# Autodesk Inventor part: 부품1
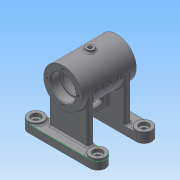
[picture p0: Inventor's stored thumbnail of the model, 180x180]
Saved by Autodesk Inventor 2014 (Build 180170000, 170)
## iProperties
Created: 2015-11
Part Number: 부품1
Material: 일반
Document SubType Name: Modeling
Designer: net
Density: 1 g/cm^3
Appearance: 기본값
Author: net
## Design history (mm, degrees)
sketch "스케치1"
  geometry: L1 (-40, -10)-(40, -10); L2 (40, 10)-(-40, 10); L3 (-40, -10)-(35.294, 8.824); L4 (40, -10)-(-40, 10); C1 r 3 at (-40, 0); C2 r 3 at (40, 0); A1 r 10 centre (-40, 0) between (-40, 10) and (-40, -10); A2 r 10 centre (40, 0) between (40, -10) and (40, 10); 1 further point
  constraints: 8 end point, 4 centre point, 4 point on circle, 2 coincident, 2 equal radius, 2 parallel, 2 tangent, 1 horizontal, 1 midpoint, 1 point on line
  dimensions: "d15" = 100 dimension on A2 A1; "d18" = 10 radius of A1; "d19" = 6 diameter of C1; "d20" = 151.928 deg angle of L3 L4; "d21" = 17.12016 distance from line of L3.end L4
extrude "돌출1" new body sketch "스케치1" distance "d22" = 10; taper "d23" = 0 deg
sketch "스케치2"
  geometry: C1 r 3 at (40, 0) reference; C2 r 3 at (-40, 0) reference; C3 r 10 at (-40, 0); C4 r 10 at (40, 0); A1 r 10 centre (-40, 0) between (-40, 10) and (-40, -10) reference; A2 r 10 centre (40, 0) between (40, -10) and (40, 10) reference; 1 further point
  constraints: 2 centre point, 2 coincident
  dimensions: "d24" = 20 diameter of C3; "d25" = 20 diameter of C4
extrude "돌출2" join sketch "스케치2" distance "d26" = 3; taper "d27" = 0 deg
sketch "스케치3"
  geometry: L1 (80, 0)-(0, 0) reference; L2 (15, 68)-(65, 68); L3 (65, 68)-(65, 0); L4 (65, 0)-(15, 0); L5 (15, 0)-(15, 68); 2 further points
  constraints: 8 end point, 2 midpoint, 2 parallel, 1 horizontal, 1 perpendicular
  dimensions: "d28" = 50 distance of L3.end L4.end; "d29" = 68 distance between parallel lines of L4 L2
extrude "돌출3" join sketch "스케치3" distance "d30" = 8; taper "d31" = 0 deg
sketch "스케치4"
  geometry: L1 (-40, -50)-(40, -50); L2 (40, -50)-(40, -70); L3 (40, -70)-(-40, -70); L4 (-40, -70)-(-40, -50); C1 r 3 at (-40, -60); C2 r 3 at (40, -60); 3 further points
  constraints: 8 end point, 2 centre point, 2 coincident, 2 midpoint, 2 parallel, 2 vertical alignment, 1 equal radius, 1 horizontal, 1 perpendicular, 4 other
  dimensions: "d34" = 80 distance between parallel lines of L2 L4; "d35" = 20 distance between parallel lines of L3 L1; "d36" = 40 distance from line of point (0, 0) L4 (= 0.5 x d34); "d37" = 50 distance from line of L1 point (0, 0); "d38" = 6 diameter of C1
extrude "돌출4" join sketch "스케치4" distance "d39" = 10; taper "d40" = 0 deg
sketch "스케치5"
  geometry: L1 (-40, -70)-(40, -70) reference; L2 (40, -50)-(-40, -50) reference; A1 r 10 centre (40, -60) between (40, -70) and (40, -50) reference; A2 r 10 centre (-40, -60) between (-40, -50) and (-40, -70) reference; 1 further point
extrude "돌출5" join sketch "스케치4" distance "d41" = 13; taper "d42" = 0 deg
extrude "돌출6" cut sketch "스케치4" stored distance "d43" = 13; taper "d44" = 0 deg
sketch "스케치6"
  geometry: L1 (0, 0)-(80, 0) reference; L2 (15, -68)-(65, -68); L3 (65, -68)-(65, 0); L4 (65, 0)-(15, 0); L5 (15, 0)-(15, -68); 1 further point
  constraints: 8 end point, 2 parallel, 1 horizontal, 1 perpendicular, 1 point on line
  dimensions: "d45" = 50 distance between parallel lines of L3 L5; "d46" = 68 distance between parallel lines of L2 L1; "d47" = 25 distance from line of point (40, 0) L5 (= 0.5 x d45)
extrude "돌출7" join sketch "스케치6" distance "d48" = 8; taper "d49" = 0 deg
node "작업 평면1"
node "작업 평면2"
sketch "스케치8"
  geometry: L1 (0, -40)-(0, -48) reference; L2 (0, 0)-(0, 8) reference; L3 (-25, -55)-(0, -55); L4 (0, -55)-(0, 15); L5 (0, 15)-(-25, 15); L6 (-25, 15)-(-25, -55); L7 (45, 0)-(45, -40) reference; L8 (45, -20)-(-11.349, -20); L9 (68, -60)-(68, -40) reference; L10 (68, 0)-(68, 20) reference; 2 further points
  constraints: 10 end point, 2 horizontal, 2 midpoint, 2 parallel, 1 perpendicular, 1 point on line
  dimensions: "d60" = 70 distance of L5.end L3.start; "d61" = 25 distance of L3.start L3.end; "d62" = 56.34938 distance of L8.start L8.end; "d64" = 68 distance between parallel lines of L10 L4
revolve "회전1" sketch "스케치8" stored, may be unused: angle "d65" = 90 deg
node "작업 평면3"
sketch "스케치10"
  geometry: L1 (-83, -7)-(-83, 63) reference; L2 (-33, -7)-(-33, 63) reference; L3 (-33, -7)-(-83, -7) reference; L4 (-58, -7)-(-58, 63); L5 (-33, 63)-(-83, 63) reference; L6 (-58, 7)-(-79, 7); L7 (-79, 7)-(-79, 49); L8 (-79, 49)-(-58, 49); 1 further point
  constraints: 8 end point, 2 horizontal, 2 midpoint, 2 point on line, 1 vertical
  dimensions: "d72" = 42 distance between parallel lines of L8 L6; "d73" = 14 distance between parallel lines of L6 L3; "d74" = 42 diameter of L7 L4
revolve "회전2" sketch "스케치10" stored, may be unused: angle "d75" = 90 deg
hole "구멍1" diameter "d78" = 28; stored, may be unused: countersink angle "d82" = 90 deg, drill point angle "d84" = 0 deg; dims "d76" = 10, "d77" = 10, "d79" = 6, "d80" = 32, "d81" = 12, "d83" = 14
hole "구멍2" diameter "d87" = 28; stored, may be unused: countersink angle "d91" = 90 deg, drill point angle "d93" = 0 deg; dims "d85" = 10, "d86" = 10, "d88" = 6, "d89" = 32, "d90" = 12, "d92" = 14
node "작업 평면4"
sketch "스케치11"
  geometry: L1 (0, -50)-(0, -10) reference; C1 r 5 at (0, -30); 1 further point
  constraints: 1 centre point, 1 midpoint
  dimensions: "d95" = 10 diameter of C1
extrude "돌출9" join sketch "스케치11" stored distance "d96" = 8; taper "d97" = 0 deg
node "작업 평면5"
sketch "스케치12"
  geometry: L1 (40, -68)-(15, -68); L2 (40, -68)-(15.751, -54); C1 r 16 at (40, -68) reference; 1 further point
  constraints: 4 end point, 1 horizontal, 1 horizontal alignment
  dimensions: "d98" = 30 deg angle of L2 L1; "d99" = 28 distance of L1.start L2.end
  node "투영된 루프4"
node "작업 평면6"
sketch "스케치13"
  geometry: L1 (-35, 25)-(-35, -25) reference; C1 r 6 at (0, 0); 1 further point
  constraints: 1 centre point
  dimensions: "d100" = 12 diameter of C1; "d101" = 66.09085 distance of C1.centre point (-30, -58.89); "d102" = 35 distance from line of C1.centre L1
extrude "돌출10" join sketch "스케치13" stored distance "d103" = 8; taper "d104" = 0 deg
hole "구멍3" diameter "d107" = 4.917; stored, may be unused: countersink angle "d111" = 90 deg, drill point angle "d113" = 118 deg; dims "d105" = 10, "d106" = 10, "d108" = 6, "d109" = 32, "d110" = 12, "d112" = 14
hole "구멍4" diameter "d116" = 4.917; stored, may be unused: countersink angle "d120" = 90 deg, drill point angle "d122" = 118 deg; dims "d114" = 10, "d115" = 10, "d117" = 6, "d118" = 32, "d119" = 12, "d121" = 14
sketch "스케치14"
  geometry: C1 r 16 at (0, 0) reference; 2 further points
  constraints: 1 vertical alignment
  dimensions: "d123" = 20 distance of C1.centre point (0, 20)
hole "구멍5" sketch "스케치14" at (0, 20) diameter "d124" = 3.242; stored, may be unused: countersink angle "d128" = 90 deg, drill point angle "d130" = 118 deg; dims "d125" = 8, "d126" = 32, "d127" = 12, "d129" = 10
node "작업 평면7"
sketch "스케치15"
  geometry: C1 r 3 at (0, 0) reference; C2 r 10 at (0, 0) reference; 1 further point
hole "구멍6" diameter "d136" = 12; stored, may be unused: countersink angle "d140" = 90 deg, drill point angle "d142" = 0 deg; dims "d134" = 10, "d135" = 10, "d137" = 8, "d138" = 32, "d139" = 12, "d141" = 4
hole "구멍7" diameter "d145" = 12; stored, may be unused: countersink angle "d149" = 90 deg, drill point angle "d151" = 0 deg; dims "d143" = 10, "d144" = 10, "d146" = 8, "d147" = 32, "d148" = 12, "d150" = 4
hole "구멍8" diameter "d154" = 12; stored, may be unused: countersink angle "d158" = 90 deg, drill point angle "d160" = 0 deg; dims "d152" = 10, "d153" = 10, "d155" = 8, "d156" = 32, "d157" = 12, "d159" = 4
hole "구멍9" diameter "d163" = 12; stored, may be unused: countersink angle "d167" = 90 deg, drill point angle "d169" = 0 deg; dims "d161" = 10, "d162" = 10, "d164" = 8, "d165" = 32, "d166" = 12, "d168" = 4
fillet "모깎기1" dims "d170" = 2
fillet "모깎기2" dims "d171" = 2
node "작업 평면8"
sketch "스케치16"
  geometry: L1 (-48.202, 6)-(0, 6) reference; L2 (10, 59)-(10, 53) reference; L3 (10, -1)-(10, -7) reference; L4 (0, 46)-(-48.202, 46) reference; L5 (-35, 6)-(-13, 6); L6 (-13, 6)-(-13, 46); L7 (-13, 46)-(-35, 46); L8 (-35, 46)-(-35, 6); L9 (10, 46)-(10, 66) reference; L10 (-23, 18)-(-23, 34); L11 (-19.5, 18)-(-19.5, 34); L12 (-26.5, 34)-(-26.5, 18); A1 r 3.5 centre (-23, 18) between (-26.5, 18) and (-19.5, 18); A2 r 3.5 centre (-23, 34) between (-19.5, 34) and (-26.5, 34); 2 further points
  constraints: 16 end point, 4 point on circle, 4 tangent, 3 parallel, 2 centre point, 2 point on line, 1 horizontal, 1 midpoint, 1 perpendicular, 1 vertical
  dimensions: "d190" = 23 distance between parallel lines of L9 L6; "d191" = 22 distance between parallel lines of L6 L8; "d192" = 3.5 radius of A2; "d193" = 23 dimension on A2 A1; "d194" = 20 distance from line of point (-23, 26) L5; "d195" = 33 distance between parallel lines of L9 L10
extrude "돌출11" join sketch "스케치16" stored distance "d196" = 8; taper "d197" = 0 deg
fillet "모깎기4" dims "d198" = 2
fillet "모깎기5" dims "d199" = 2
fillet "모깎기6" dims "d200" = 2
fillet "모깎기7" dims "d201" = 2
fillet "모깎기8" dims "d202" = 2
fillet "모깎기9" dims "d203" = 2
fillet "모깎기10" dims "d204" = 3
fillet "모깎기11" dims "d205" = 0.3
node "작업 평면10"
sketch "스케치17"
  geometry: L1 (-65, 93)-(5, 93) reference; L2 (-65, 43)-(-65, 93) reference; 2 further points
  constraints: 1 other
  dimensions: "d208" = 25 distance from line of point (-30, 68) L1; "d209" = 35 distance from line of point (-30, 68) L2
feature "엠보싱1" sketch "스케치17" dims "d210" = 0.5, "d211" = 0
chamfer "모따기1" distance "d212" = 1; stored, may be unused: second distance "d213" = 2, angle "d214" = 45 deg
node "솔리드1"
pattern_circular "원형 패턴1" dims angle "d132" = 360 deg
mirror "대칭1"
other parameters: "d94" = -96, "d207" = 26
